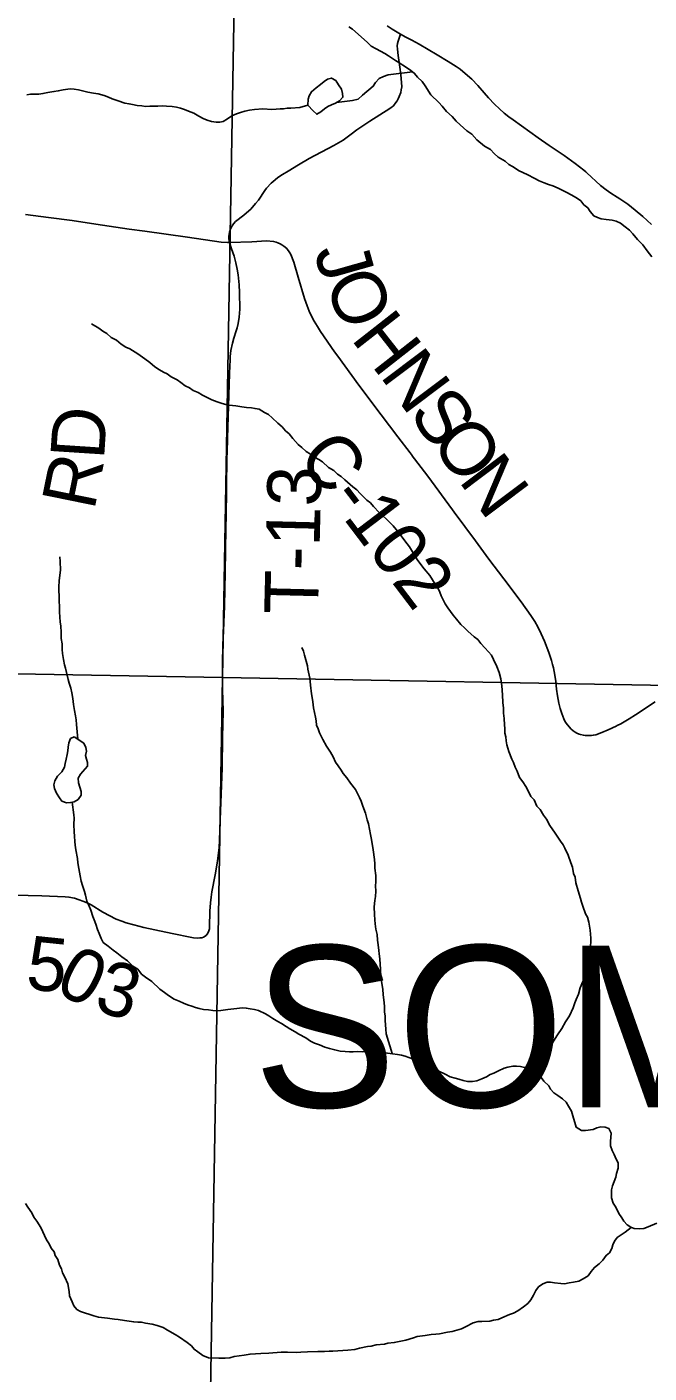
# Model space of a CAD drawing. Extents: x 0 to 34, y 0 to 22.
# Drawn here: x 28.673 to 29.33, y 16.803 to 18.224 of the extents above; entities that cross this region are included whole.
import ezdxf

# ---------------------------------------------------------------- set-up
doc = ezdxf.new("R2010")
doc.units = 0
for name, color, linetype in [('GM_X_Corporation', 7, 'Continuous'), ('GM_X_County_Road', 7, 'Continuous'), ('GM_X_County_Road_Text', 7, 'Continuous'), ('GM_X_Minor_River', 7, 'Continuous'), ('GM_X_Township_Road', 7, 'Continuous'), ('GM_X_Township_Road_Text', 7, 'Continuous'), ('GM_X_Township_Text', 7, 'Continuous')]:
    doc.layers.add(name, color=color, linetype=linetype)

msp = doc.modelspace()

# ---------------------------------------------------------------- linework, layer by layer
at = {"layer": 'GM_X_Corporation'}
for points in [[(28.8973, 18.5532), (28.8799, 17.5369), (27.873, 17.5549), (27.8861, 18.5601)], [(29.9261, 18.5329), (29.9011, 17.5188), (28.8799, 17.5369), (28.8973, 18.5532)], [(27.873, 17.5549), (28.8799, 17.5369), (28.863, 16.5324), (27.8467, 16.5483)], [(28.8799, 17.5369), (29.9011, 17.5188), (29.8741, 16.51), (28.863, 16.5324)]]:
    msp.add_lwpolyline(points, close=True, dxfattribs=at)
at = {"layer": 'GM_X_County_Road'}
msp.add_lwpolyline([(28.672, 18.0255), (28.6963, 18.0226), (28.7213, 18.0192), (28.7463, 18.0154), (28.7812, 18.0101), (28.7977, 18.008), (28.843, 18.0018), (28.8784, 17.9964), (28.885, 17.9961), (28.8873, 17.9961), (28.9109, 17.9967), (28.9263, 17.9978), (28.9337, 17.9972), (28.9365, 17.9965), (28.9384, 17.9958), (28.9408, 17.9947), (28.9425, 17.9937), (28.9445, 17.9923), (28.9478, 17.9896), (28.9511, 17.9853), (28.9521, 17.9834), (28.955, 17.9754), (28.9596, 17.9595), (28.9665, 17.9369), (28.9691, 17.9293), (28.9714, 17.9237), (28.9738, 17.9185), (28.9766, 17.9132), (28.98, 17.9073), (28.9833, 17.9021), (28.9982, 17.8806), (29.0015, 17.876), (29.0237, 17.8455), (29.0473, 17.8143), (29.065, 17.7912), (29.0779, 17.774), (29.0799, 17.7715), (29.0801, 17.7711), (29.0826, 17.7679), (29.0965, 17.7497), (29.1228, 17.7141), (29.1245, 17.7117), (29.147, 17.6812), (29.1609, 17.6621), (29.177, 17.6412), (29.1951, 17.617), (29.2054, 17.6025), (29.2095, 17.596), (29.2128, 17.5904), (29.2164, 17.5832), (29.2198, 17.5754), (29.2244, 17.5635), (29.2272, 17.5549), (29.2283, 17.5509), (29.2293, 17.5472), (29.2308, 17.5397), (29.2319, 17.533), (29.2326, 17.5247), (29.2336, 17.5176), (29.235, 17.5101), (29.2363, 17.5045), (29.2379, 17.4991), (29.239, 17.4962), (29.2401, 17.4936), (29.2414, 17.4911), (29.2427, 17.4889), (29.2474, 17.4829), (29.2501, 17.4807), (29.2523, 17.4793), (29.254, 17.4784), (29.2565, 17.4772), (29.2577, 17.4768), (29.2608, 17.4761), (29.2628, 17.4758), (29.2657, 17.4757), (29.2678, 17.4758), (29.2694, 17.4759), (29.2713, 17.4761), (29.2741, 17.4767), (29.2802, 17.4789), (29.287, 17.4817), (29.2953, 17.4856), (29.2965, 17.4863), (29.3004, 17.4883), (29.309, 17.4934), (29.3159, 17.4978), (29.3365, 17.5113)], dxfattribs=at)
at = {"layer": 'GM_X_Minor_River'}
for points in [[(29.0132, 18.2238), (29.017, 18.2212), (29.0324, 18.2074), (29.0367, 18.2033), (29.042, 18.2004), (29.0512, 18.1956), (29.055, 18.193), (29.0623, 18.1882), (29.0661, 18.186), (29.0703, 18.1831), (29.0741, 18.1809), (29.0787, 18.1775), (29.0826, 18.1746), (29.0857, 18.1705)], [(28.9699, 18.1411), (28.9703, 18.1472), (28.9714, 18.151), (28.9739, 18.1552), (28.9788, 18.1594), (28.9833, 18.1629), (28.987, 18.166), (28.9907, 18.1684), (28.9949, 18.1696), (28.9995, 18.167), (29.0022, 18.1625), (29.0053, 18.158), (29.0065, 18.1535), (29.007, 18.1493), (29.0032, 18.1455), (28.9991, 18.1431), (28.995, 18.1415), (28.9912, 18.1396), (28.9875, 18.1372), (28.9838, 18.1341), (28.9793, 18.1314), (28.9754, 18.1351), (28.9699, 18.1411)], [(29.0003, 18.1438), (29.017, 18.1458), (29.0229, 18.1473), (29.0277, 18.1516), (29.0389, 18.1609), (29.0415, 18.1651), (29.0452, 18.169), (29.0497, 18.1713), (29.0546, 18.1729), (29.0804, 18.1763)], [(29.0857, 18.1705), (29.0907, 18.166), (29.0938, 18.1615), (29.0996, 18.1521), (29.1081, 18.1439), (29.1116, 18.1398), (29.1162, 18.1342), (29.1223, 18.129), (29.1266, 18.1242), (29.1308, 18.1201), (29.1377, 18.1141), (29.1431, 18.1104), (29.1485, 18.1044), (29.1566, 18.0978), (29.1627, 18.0941), (29.1665, 18.09), (29.1708, 18.0863), (29.1784, 18.0818), (29.1822, 18.0785), (29.1861, 18.0763), (29.193, 18.0719), (29.2014, 18.0678), (29.2094, 18.0638), (29.2143, 18.0613), (29.2193, 18.0591), (29.2239, 18.0573), (29.2284, 18.0558), (29.2342, 18.0533), (29.2433, 18.0489), (29.2479, 18.0463), (29.2536, 18.0434), (29.2582, 18.04), (29.2613, 18.0359), (29.2655, 18.0326), (29.2679, 18.0288), (29.2717, 18.0244), (29.2756, 18.0225), (29.2797, 18.0211), (29.2847, 18.0204), (29.2911, 18.0198), (29.2953, 18.0187), (29.2999, 18.0165), (29.3049, 18.0128), (29.3095, 18.0091), (29.3129, 18.0054), (29.318, 17.9994), (29.3234, 17.9938), (29.328, 17.9874), (29.333, 17.9811)], [(28.6732, 18.1521), (28.6773, 18.1525), (28.686, 18.1527), (28.6902, 18.1532), (28.6955, 18.1544), (28.7019, 18.1553), (28.7064, 18.1561), (28.7117, 18.1573), (28.7192, 18.1582), (28.7234, 18.1579), (28.728, 18.1572), (28.7333, 18.1558), (28.7378, 18.1548), (28.7435, 18.1537), (28.7485, 18.1531), (28.7549, 18.1513), (28.7595, 18.1495), (28.7633, 18.1476), (28.7698, 18.1455), (28.7766, 18.1433), (28.7812, 18.1423), (28.785, 18.1416), (28.7899, 18.1405), (28.7948, 18.1402), (28.7986, 18.1395), (28.8032, 18.14), (28.8077, 18.1401), (28.8115, 18.1398), (28.816, 18.1402), (28.8206, 18.1399), (28.8266, 18.1397), (28.8312, 18.139), (28.8354, 18.1379), (28.8396, 18.1365), (28.8438, 18.1347), (28.8495, 18.1325), (28.8548, 18.1295), (28.8594, 18.127), (28.8636, 18.1251), (28.8682, 18.1237), (28.8731, 18.123), (28.8769, 18.1231), (28.8806, 18.1239), (28.8851, 18.1267), (28.8896, 18.1298), (28.8945, 18.1318), (28.899, 18.1334), (28.9035, 18.1346), (28.9084, 18.1358), (28.9137, 18.1363), (28.9224, 18.1372), (28.9319, 18.1366), (28.9364, 18.1367), (28.9406, 18.1371), (28.9444, 18.1372), (28.9481, 18.1377), (28.9519, 18.1377), (28.9614, 18.1387), (28.9699, 18.1411)], [(28.7417, 17.9102), (28.7494, 17.9058), (28.7536, 17.9025), (28.7578, 17.8999), (28.7624, 17.8958), (28.7678, 17.8929), (28.7728, 17.8888), (28.7777, 17.8858), (28.7819, 17.884), (28.7903, 17.8785), (28.798, 17.8733), (28.803, 17.8696), (28.8084, 17.8648), (28.8133, 17.8618), (28.8175, 17.8592), (28.8214, 17.8574), (28.8256, 17.8545), (28.8321, 17.8512), (28.8359, 17.8482), (28.8405, 17.8449), (28.8451, 17.8427), (28.8489, 17.8401), (28.8542, 17.8379), (28.8588, 17.835), (28.8687, 17.8302), (28.8741, 17.828), (28.8794, 17.8262), (28.8832, 17.8252), (28.887, 17.8245), (28.8938, 17.8238), (28.9003, 17.8228), (28.9052, 17.8221), (28.9105, 17.8215), (28.9143, 17.8208), (28.9185, 17.8201), (28.9242, 17.8168), (28.9284, 17.8146), (28.9323, 17.8112), (28.9384, 17.8053), (28.9427, 17.8016), (28.9465, 17.7975), (28.9503, 17.7941), (28.9542, 17.7893), (28.9596, 17.7829), (28.9635, 17.7799), (28.9681, 17.7755), (28.9727, 17.7729), (28.9769, 17.7696), (28.9815, 17.767), (28.9853, 17.7648), (28.9918, 17.7588), (28.9972, 17.7555), (29.0014, 17.7518), (29.0052, 17.7492), (29.0091, 17.7455), (29.0175, 17.7381), (29.0218, 17.7351), (29.0252, 17.7314), (29.0322, 17.7243), (29.036, 17.7213), (29.0391, 17.7176), (29.0453, 17.7113), (29.0529, 17.7042), (29.0599, 17.6971), (29.0664, 17.6893), (29.0723, 17.6814), (29.0773, 17.675), (29.0792, 17.6713), (29.082, 17.6672), (29.0862, 17.6604), (29.0928, 17.6518), (29.0986, 17.6447), (29.1045, 17.6357), (29.1072, 17.6316), (29.1092, 17.6271), (29.1107, 17.6233), (29.1131, 17.6184), (29.115, 17.6147), (29.1178, 17.6105), (29.1205, 17.6068), (29.1232, 17.6027), (29.1267, 17.5986), (29.1313, 17.593), (29.1352, 17.5896), (29.139, 17.5859), (29.1455, 17.58), (29.1494, 17.577), (29.1525, 17.5729), (29.1567, 17.5684), (29.1606, 17.5643), (29.1637, 17.5606), (29.166, 17.5561), (29.1695, 17.5485), (29.1719, 17.5425), (29.1736, 17.5357), (29.1748, 17.5281), (29.1754, 17.5187), (29.1759, 17.5107), (29.1764, 17.5047), (29.1765, 17.4994), (29.1773, 17.4937)], [(28.7082, 17.6643), (28.7086, 17.6594), (28.7088, 17.6503), (28.7081, 17.6449), (28.7075, 17.6392), (28.7072, 17.6328), (28.7069, 17.6282), (28.7074, 17.6237), (28.7077, 17.6059), (28.7081, 17.601), (28.7086, 17.5953), (28.7091, 17.5915), (28.7096, 17.5847), (28.7097, 17.5782), (28.7105, 17.5726), (28.7106, 17.5665), (28.7111, 17.5623), (28.712, 17.5559), (28.7132, 17.5506), (28.714, 17.5468), (28.7152, 17.5423), (28.7169, 17.5351), (28.7181, 17.531), (28.7197, 17.5257), (28.7209, 17.5208), (28.7218, 17.5148), (28.7226, 17.5087), (28.7235, 17.5023), (28.7247, 17.4966), (28.7252, 17.4924), (28.7256, 17.4875), (28.7271, 17.472)], [(28.9637, 17.5687), (28.9653, 17.565), (28.9665, 17.5608), (28.9694, 17.5495), (28.9698, 17.5457), (28.9719, 17.5363), (28.9728, 17.5291), (28.9737, 17.52), (28.9745, 17.5158), (28.9753, 17.5113), (28.9758, 17.5049), (28.977, 17.5), (28.9779, 17.4951), (28.9787, 17.4913), (28.9792, 17.4867), (28.9807, 17.483), (28.9823, 17.4785), (28.9859, 17.4717), (28.9898, 17.4646), (28.994, 17.4582), (28.9968, 17.4533), (28.9991, 17.4477), (29.0019, 17.4439), (29.005, 17.4394), (29.0073, 17.4357), (29.0112, 17.4312), (29.015, 17.4256), (29.0201, 17.4188), (29.0244, 17.4106), (29.0263, 17.4064), (29.0279, 17.4012), (29.0307, 17.394), (29.0327, 17.3868), (29.0339, 17.3827), (29.0352, 17.377), (29.036, 17.3714), (29.0373, 17.3661), (29.039, 17.3551), (29.0403, 17.3449), (29.0407, 17.3403), (29.0408, 17.3358), (29.0417, 17.3282), (29.0418, 17.3214), (29.0415, 17.3172), (29.0416, 17.3115), (29.0413, 17.3059), (29.0407, 17.3017), (29.04, 17.2952), (29.0402, 17.2869), (29.0406, 17.2812), (29.0411, 17.277), (29.0416, 17.2714), (29.0432, 17.2657), (29.0436, 17.26), (29.0441, 17.2551), (29.045, 17.249), (29.0454, 17.2453), (29.0459, 17.2403), (29.0464, 17.2343), (29.0468, 17.2297), (29.047, 17.2206), (29.0483, 17.2123), (29.0491, 17.2078), (29.0496, 17.2025), (29.0505, 17.1938), (29.0509, 17.19), (29.051, 17.1843), (29.0515, 17.1798), (29.0516, 17.1752), (29.052, 17.1707), (29.0521, 17.1658), (29.0526, 17.1612), (29.059, 17.1402)], [(29.1773, 17.4937), (29.1774, 17.4872), (29.1779, 17.4831), (29.178, 17.4782), (29.1788, 17.4744), (29.1792, 17.4702), (29.1801, 17.4661), (29.1821, 17.4589), (29.1852, 17.451), (29.1872, 17.4472), (29.1888, 17.4423), (29.1908, 17.4382), (29.1935, 17.4314), (29.197, 17.4269), (29.2001, 17.4221), (29.2025, 17.4176), (29.2052, 17.4115), (29.2087, 17.4078), (29.2118, 17.4014), (29.2153, 17.3977), (29.2188, 17.3917), (29.2219, 17.3876), (29.2254, 17.3808), (29.2309, 17.3729), (29.2367, 17.3643), (29.2394, 17.3606), (29.2414, 17.3568), (29.2449, 17.3497), (29.2477, 17.3414), (29.2493, 17.3369), (29.2505, 17.3304), (29.2521, 17.3263), (29.253, 17.3203), (29.2554, 17.312), (29.2578, 17.3037), (29.259, 17.2999), (29.2602, 17.2957), (29.263, 17.2878), (29.265, 17.2841), (29.2666, 17.2788), (29.2678, 17.2705), (29.2687, 17.2621), (29.2688, 17.2584), (29.2685, 17.2534), (29.2678, 17.2489), (29.2672, 17.2435), (29.2661, 17.2397), (29.2654, 17.2348), (29.264, 17.2302), (29.2629, 17.226), (29.2615, 17.2218), (29.2601, 17.2161), (29.2575, 17.2096), (29.2558, 17.2028), (29.2532, 17.1974), (29.2518, 17.1936), (29.25, 17.1886), (29.246, 17.1802), (29.2419, 17.1737), (29.2379, 17.1668), (29.2334, 17.1599), (29.2294, 17.1534), (29.2264, 17.1488), (29.2235, 17.1442), (29.2198, 17.1396)], [(28.7232, 17.4746), (28.7335, 17.4676), (28.7355, 17.4631), (28.7363, 17.4593), (28.7353, 17.4547), (28.7361, 17.4509), (28.7373, 17.4472), (28.7374, 17.4434), (28.73, 17.4349), (28.7274, 17.4307), (28.7278, 17.4258), (28.7291, 17.4212), (28.7307, 17.4167), (28.7307, 17.4129), (28.7274, 17.4083), (28.7233, 17.406), (28.7195, 17.4051), (28.715, 17.4047), (28.7104, 17.4065), (28.7077, 17.4102), (28.7046, 17.4151), (28.7026, 17.42), (28.7018, 17.4238), (28.7028, 17.428), (28.7058, 17.433), (28.7102, 17.4376), (28.7132, 17.4426), (28.7139, 17.4464), (28.7149, 17.4509), (28.716, 17.4559), (28.7167, 17.4597), (28.717, 17.4635), (28.7176, 17.468), (28.7195, 17.4726), (28.7232, 17.4746)], [(28.7213, 17.4055), (28.7228, 17.3923), (28.7232, 17.3885), (28.7229, 17.3821), (28.7231, 17.3741), (28.7235, 17.3696), (28.724, 17.3639), (28.7244, 17.3601), (28.7249, 17.3552), (28.7266, 17.3461), (28.727, 17.3416), (28.7283, 17.3355), (28.7296, 17.3276), (28.7308, 17.3223), (28.732, 17.3174), (28.734, 17.3114), (28.7352, 17.3072), (28.7368, 17.3012), (28.7392, 17.2959), (28.7408, 17.2914), (28.7428, 17.285), (28.7444, 17.2812), (28.7463, 17.2767), (28.7479, 17.271), (28.7495, 17.2669), (28.7519, 17.2616), (28.7539, 17.2575), (28.7592, 17.2534), (28.7646, 17.2494), (28.7684, 17.2464), (28.7734, 17.2423), (28.7795, 17.2379), (28.7853, 17.2323), (28.7903, 17.2293), (28.7945, 17.2241), (28.7984, 17.2208), (28.8053, 17.2163), (28.8137, 17.2081), (28.8187, 17.2048), (28.8229, 17.2015), (28.8287, 17.1978), (28.834, 17.1956), (28.8386, 17.1934), (28.8428, 17.1916), (28.8473, 17.1902), (28.8515, 17.1887), (28.8553, 17.1877), (28.8599, 17.1866), (28.8652, 17.1863), (28.8698, 17.1856), (28.8739, 17.1853), (28.8781, 17.1858), (28.8856, 17.1867), (28.8917, 17.1875), (28.9011, 17.1885), (28.9049, 17.1882), (28.9091, 17.1875), (28.9136, 17.1868), (28.9178, 17.1857), (28.9251, 17.1821), (28.9289, 17.1799), (28.9331, 17.1773), (28.9381, 17.174), (28.9423, 17.1721), (28.9469, 17.1688), (28.9511, 17.1662), (28.9564, 17.1633), (28.9606, 17.1607), (28.9679, 17.1567), (28.9729, 17.1534), (28.9771, 17.1512), (28.9824, 17.1494), (28.9877, 17.1468), (28.9927, 17.1454), (28.9984, 17.144), (29.0041, 17.1429), (29.0094, 17.1423), (29.0139, 17.142), (29.0177, 17.142), (29.0222, 17.1425), (29.0275, 17.1422), (29.037, 17.1424), (29.0453, 17.1418), (29.0491, 17.1414), (29.054, 17.1408), (29.0594, 17.1401), (29.0647, 17.1391), (29.0688, 17.1384), (29.0726, 17.1373), (29.0765, 17.1359), (29.0803, 17.1348), (29.0844, 17.1337), (29.0943, 17.1294), (29.0997, 17.1264), (29.1039, 17.1238), (29.1081, 17.1216), (29.115, 17.1184), (29.1203, 17.1158), (29.1256, 17.1144), (29.1294, 17.1133), (29.134, 17.1119)], [(29.134, 17.1119), (29.1386, 17.1108), (29.1439, 17.1109), (29.1484, 17.1114), (29.1537, 17.1134), (29.1585, 17.1157), (29.1623, 17.1181), (29.1664, 17.1197), (29.1713, 17.122), (29.1773, 17.1248), (29.1811, 17.126), (29.1863, 17.1268), (29.1901, 17.1269), (29.1943, 17.1266), (29.1988, 17.1255), (29.2027, 17.1237), (29.2069, 17.1215), (29.2111, 17.1186), (29.2161, 17.1149), (29.2192, 17.1111), (29.2242, 17.1063), (29.2261, 17.1025), (29.2296, 17.0988), (29.2338, 17.0958), (29.2388, 17.0925), (29.2426, 17.0888), (29.245, 17.0847), (29.2481, 17.0794), (29.2505, 17.0719), (29.2517, 17.0673), (29.2533, 17.0624), (29.2587, 17.0591), (29.2632, 17.0592), (29.2711, 17.0601), (29.2749, 17.0617), (29.2794, 17.0629), (29.2839, 17.0626), (29.2878, 17.0612), (29.2901, 17.0563), (29.2898, 17.0517), (29.2895, 17.0479), (29.2896, 17.043), (29.2912, 17.0381), (29.2932, 17.0336), (29.2955, 17.0287), (29.2975, 17.0249), (29.2976, 17.0193), (29.2958, 17.0135), (29.2951, 17.0097), (29.2915, 17.0006), (29.2904, 16.9964), (29.2905, 16.9881), (29.2921, 16.9824), (29.2949, 16.9783), (29.2984, 16.9715), (29.3015, 16.967), (29.3035, 16.9633), (29.3069, 16.9595), (29.3108, 16.9569), (29.3146, 16.9555), (29.3199, 16.9552), (29.3248, 16.9557), (29.3293, 16.9573), (29.3383, 16.9612)], [(28.672, 16.9819), (28.6743, 16.9782), (28.6786, 16.9722), (28.6806, 16.9677), (28.6837, 16.9632), (28.6879, 16.9568), (28.6942, 16.9437), (28.6969, 16.9395), (28.6989, 16.9347), (28.702, 16.9309), (28.7032, 16.9271), (28.7059, 16.923), (28.7079, 16.917), (28.7099, 16.9129), (28.7111, 16.9087), (28.7134, 16.9042), (28.7166, 16.8971), (28.7179, 16.8891), (28.7183, 16.8846), (28.7211, 16.8782), (28.723, 16.874), (28.7261, 16.8703), (28.73, 16.8681), (28.744, 16.8634), (28.749, 16.862), (28.7585, 16.861), (28.7657, 16.86), (28.7698, 16.8597), (28.7763, 16.8587), (28.7862, 16.857), (28.7903, 16.8567), (28.7945, 16.8567), (28.7987, 16.8557), (28.8055, 16.8547), (28.8108, 16.8532), (28.8173, 16.8511), (28.8219, 16.8485), (28.8299, 16.8437), (28.8345, 16.8408), (28.8425, 16.8352), (28.8471, 16.8319), (28.8498, 16.8282), (28.8537, 16.8256), (28.859, 16.8215), (28.8651, 16.8193), (28.8761, 16.8188), (28.8826, 16.8189), (28.8875, 16.8193), (28.892, 16.8206), (28.9026, 16.8219), (28.909, 16.8231), (28.9203, 16.8237), (28.9286, 16.8242), (28.9418, 16.8252), (28.9483, 16.825), (28.9581, 16.8248), (28.9627, 16.8252), (28.9695, 16.8254), (28.9804, 16.8259), (28.9876, 16.8257), (28.9925, 16.8261), (28.9963, 16.8262), (29.0069, 16.8268), (29.0122, 16.8273), (29.0194, 16.8281), (29.0243, 16.8294), (29.0329, 16.831), (29.0367, 16.8315), (29.042, 16.8327), (29.0507, 16.8336), (29.0544, 16.8345), (29.0612, 16.8353), (29.0733, 16.8378), (29.0816, 16.8402), (29.0854, 16.8415), (29.0937, 16.8427), (29.1001, 16.8436), (29.105, 16.8441), (29.1088, 16.8445), (29.1174, 16.8462)], [(29.1174, 16.8462), (29.1223, 16.847), (29.1321, 16.8499), (29.1363, 16.8518), (29.1445, 16.8562), (29.1498, 16.8574), (29.1536, 16.8575), (29.1619, 16.858), (29.166, 16.8588), (29.1709, 16.8597), (29.1747, 16.8612), (29.1829, 16.8648), (29.1871, 16.8664), (29.1916, 16.8688), (29.1976, 16.873), (29.202, 16.8765), (29.2054, 16.8804), (29.2083, 16.8854), (29.2105, 16.8903), (29.2135, 16.8942), (29.2179, 16.8973), (29.2225, 16.8989), (29.2262, 16.8989), (29.2304, 16.8983), (29.2369, 16.8976), (29.241, 16.8973), (29.2459, 16.8982), (29.2505, 16.899), (29.2561, 16.9002), (29.2606, 16.9026), (29.2659, 16.9057), (29.2692, 16.9103), (29.2725, 16.9146), (29.2774, 16.9184), (29.2815, 16.9223), (29.2848, 16.9273), (29.2885, 16.93), (29.2907, 16.9346), (29.2918, 16.9384), (29.2936, 16.9422), (29.2966, 16.9461), (29.3007, 16.9488), (29.3048, 16.9519), (29.3113, 16.9567)]]:
    msp.add_lwpolyline(points, dxfattribs=at)
at = {"layer": 'GM_X_Township_Road'}
for points in [[(28.8808, 17.5864), (28.8819, 17.6125), (28.8827, 17.6482), (28.8832, 17.6943), (28.8836, 17.7086), (28.8842, 17.7333), (28.884, 17.7501), (28.8843, 17.7566), (28.8844, 17.7694), (28.8846, 17.774), (28.8852, 17.7896), (28.8861, 17.8235), (28.8874, 17.8578), (28.8877, 17.8655), (28.8878, 17.872), (28.888, 17.8757), (28.8888, 17.8822), (28.8903, 17.8897), (28.8918, 17.8951), (28.8944, 17.9028), (28.8952, 17.9059), (28.8963, 17.9105), (28.8974, 17.9173), (28.8978, 17.9216), (28.8981, 17.9256), (28.8979, 17.9433), (28.8973, 17.9516), (28.8963, 17.9619), (28.8953, 17.9681), (28.8939, 17.9748), (28.892, 17.9818), (28.8894, 17.9895), (28.8873, 17.9961), (28.8867, 17.9998), (28.8866, 18.0026), (28.8873, 18.0071), (28.8883, 18.0105), (28.89, 18.0137), (28.8915, 18.0158), (28.8936, 18.0183), (28.9023, 18.0249), (28.9052, 18.0274), (28.9096, 18.0314), (28.9148, 18.0371), (28.9178, 18.0408), (28.9246, 18.0509), (28.9264, 18.0533), (28.9313, 18.0588), (28.9353, 18.0623), (28.9383, 18.0647), (28.9432, 18.068), (28.9493, 18.0715), (28.9601, 18.078), (28.9714, 18.0847), (28.9974, 18.0986), (29.0073, 18.1042), (29.0155, 18.1103), (29.0216, 18.115), (29.0353, 18.1242), (29.0566, 18.1376), (29.0602, 18.1404), (29.063, 18.1438), (29.0642, 18.1455), (29.0653, 18.1476), (29.0665, 18.1501), (29.068, 18.1545), (29.0686, 18.1573), (29.069, 18.1604), (29.0681, 18.1735), (29.0672, 18.181), (29.0653, 18.1934), (29.0645, 18.2002), (29.0644, 18.2037), (29.0645, 18.2062), (29.0653, 18.2087), (29.0679, 18.216)], [(29.0537, 18.2249), (29.0557, 18.2234), (29.0591, 18.2213), (29.0679, 18.216), (29.0735, 18.2127), (29.0782, 18.2103), (29.0797, 18.2095), (29.0873, 18.2053), (29.1066, 18.1941), (29.1181, 18.1872), (29.1265, 18.1819), (29.1306, 18.1789), (29.1361, 18.1746), (29.143, 18.1684), (29.1495, 18.1617), (29.1559, 18.154), (29.1605, 18.1486), (29.1669, 18.142), (29.1722, 18.1371), (29.1773, 18.1327), (29.1822, 18.1288), (29.1868, 18.1254), (29.213, 18.1065), (29.2246, 18.0984), (29.2405, 18.0878), (29.2521, 18.0793), (29.2613, 18.0723), (29.2635, 18.0705), (29.2646, 18.0696), (29.2789, 18.0564), (29.2847, 18.0517), (29.2897, 18.0483), (29.2965, 18.0441), (29.2993, 18.0423), (29.3076, 18.0365), (29.3156, 18.0303), (29.3234, 18.0235), (29.328, 18.0194), (29.3326, 18.015)], [(28.8626, 17.2647), (28.8642, 17.2671), (28.8654, 17.2696), (28.866, 17.2719), (28.8661, 17.2738), (28.8665, 17.2904), (28.8671, 17.2992), (28.8678, 17.3052), (28.8686, 17.311), (28.8721, 17.3287), (28.8739, 17.3391), (28.875, 17.346), (28.8762, 17.3578), (28.8767, 17.365), (28.8774, 17.3872), (28.8789, 17.423), (28.8794, 17.4416), (28.8798, 17.4744), (28.8804, 17.5007), (28.8801, 17.514), (28.8798, 17.5232), (28.8797, 17.5519), (28.8802, 17.5714), (28.8808, 17.5864)], [(28.6601, 17.3074), (28.689, 17.3065), (28.7138, 17.3057), (28.7177, 17.3053), (28.7235, 17.3041), (28.7287, 17.3026), (28.7325, 17.3012), (28.7369, 17.2993), (28.7412, 17.2971), (28.7535, 17.2896), (28.7677, 17.2822), (28.7734, 17.2799), (28.7783, 17.2783), (28.7861, 17.2759), (28.7968, 17.2732), (28.8085, 17.2707), (28.8267, 17.267), (28.8474, 17.2628), (28.8492, 17.2625), (28.8531, 17.2621), (28.8559, 17.2622), (28.8579, 17.2625), (28.8598, 17.263), (28.8626, 17.2647)]]:
    msp.add_lwpolyline(points, dxfattribs=at)

# ---------------------------------------------------------------- texts
at = {"layer": 'GM_X_County_Road_Text'}
for s, height, rotation, p in [('J', 0.0568, 285.8488, (28.9761, 17.9873)), ('O', 0.0568, 293.9497, (28.9863, 17.9534)), ('H', 0.0568, 308.082, (29.0145, 17.8946)), ('N', 0.0568, 306.9096, (29.0451, 17.8555)), ('S', 0.0568, 306.9098, (29.0752, 17.8155)), ('D', 0.0568, 86.276, (28.7547, 17.7662)), ('O', 0.0568, 306.9087, (29.0982, 17.7849)), ('C-102', 0.05682, 307.2527, (28.9577, 17.7697)), ('N', 0.0568, 306.9107, (29.1282, 17.7449)), ('R', 0.0568, 78.483, (28.7443, 17.7123))]:
    msp.add_text(s, height=height, rotation=rotation, dxfattribs=at).set_placement(p)
at = {"layer": 'GM_X_Township_Road_Text'}
for s, height, rotation, p in [('T-13', 0.05682, 88.5881, (28.9806, 17.6032)), ('5', 0.0568, 354.1641, (28.6711, 17.2085)), ('0', 0.0568, 332.9602, (28.7006, 17.2065)), ('3', 0.0568, 343.6498, (28.7425, 17.1863))]:
    msp.add_text(s, height=height, rotation=rotation, dxfattribs=at).set_placement(p)
at = {"layer": 'GM_X_Township_Text'}
msp.add_text('SOMERSET', height=0.17045, rotation=0, dxfattribs=at).set_placement((28.9118, 17.0836))

doc.saveas('drawing.dxf')
